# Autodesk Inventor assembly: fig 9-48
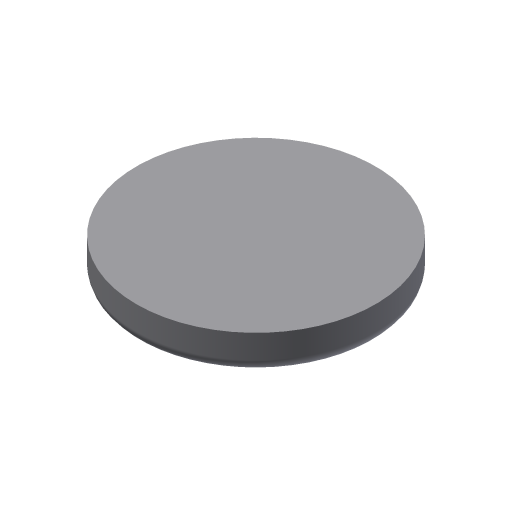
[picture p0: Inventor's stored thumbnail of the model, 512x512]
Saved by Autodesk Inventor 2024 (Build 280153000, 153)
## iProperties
Created: 2013-07
Part Number: fig 9-48
Document SubType Name: Assembly
Designer: CADCIM
Author: CADCIM
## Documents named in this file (3)
- D:\PROJECTS\Project 2023\RESOURCES INVENTOR 2024\RESOURCES INVENTOR 2024\Inventor_2023_Part\Inventor_2024_Part\c09_Inv_2024_prt\fig 9-49.iam
- E:\_Deepak\Inventor\Autodesk Inventor_2017_Project\Resources\Inventor_2018_Part\c09_Inv_2018\c09_inv_2018_prt\17 (1).ipt
- D:\PROJECTS\Project 2023\RESOURCES INVENTOR 2024\RESOURCES INVENTOR 2024\Inventor_2023_Part\Inventor_2024_Part\c09_Inv_2024_prt\18.ipt
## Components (2 placed, 2 different names)
1. 17 (1):1 — Planar:1
2. 18:1 — Planar:1
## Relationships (1: PlanarJoint 1)
- Planar:1: 17 (1):1 ↔ 18:1
